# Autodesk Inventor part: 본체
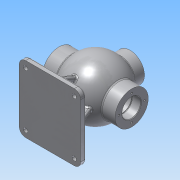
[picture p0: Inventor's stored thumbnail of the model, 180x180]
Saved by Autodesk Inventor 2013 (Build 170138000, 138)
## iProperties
Created: 2018-06
Part Number: 본체
Material: 알루미늄 6061
Document SubType Name: Modeling
Designer: Administrator
Density: 2.71 g/cm^3
Mass: 1509.58 g
Surface Area: 1153.7 cm^2
Volume: 557.041 cm^3
Author: Administrator
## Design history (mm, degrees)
sketch "스케치1"
  geometry: L1 (-68, 0)-(68, 0); L2 (-42.988, 31)-(-68, 31); L3 (-68, 31)-(-68, 17.5); L4 (-68, 17.5)-(-39.278, 17.5); L5 (42.988, 31)-(68, 31); L6 (68, 31)-(68, 17.5); L7 (50.25, 18.5)-(52, 18.5); L8 (52, 18.5)-(52, 17.5); L9 (50.25, 17.5)-(50.25, 18.5); L10 (68, 17.5)-(52, 17.5); L11 (50.25, 17.5)-(39.278, 17.5); A1 r 53 centre (0, 0) between (42.988, 31) and (-42.988, 31); A2 r 43 centre (0, 0) between (39.278, 17.5) and (-39.278, 17.5); 2 further points
  constraints: 22 end point, 6 parallel, 4 point on circle, 3 coincident, 3 perpendicular, 2 centre point, 2 horizontal, 2 point on line, 1 collinear, 1 midpoint
  dimensions: "d0" = 136 distance of L1.start L1.end; "d2" = 106 diameter of A1; "d3" = 86 diameter of A2; "d4" = 35 diameter of L4 L1; "d5" = 62 diameter of L2 L1; "d7" = 62 diameter of L5 L1; "d8" = 37 diameter of L7 L1; "d9" = 16 distance between parallel lines of L8 L6; "d10" = 1.75 distance of L7.start L7.end; "d11" = 35 diameter of L10 L1
revolve "회전1" sketch "스케치1" stored, may be unused: angle "d12" = 90 deg
sketch "스케치2"
  geometry: L1 (-57.5, -75)-(57.5, -75); L2 (57.5, -75)-(57.5, -85); L3 (57.5, -85)-(-57.5, -85); L4 (-57.5, -85)-(-57.5, -75); 2 further points
  constraints: 8 end point, 2 parallel, 1 horizontal, 1 midpoint, 1 perpendicular, 1 vertical alignment
  dimensions: "d13" = 115 distance of L2.end L3.end; "d15" = 85 distance from line of point (0, 0) L3; "d16" = 10 distance of L1.end L2.end
extrude "돌출1" join sketch "스케치2" stored distance "d17" = 125; taper "d18" = 0 deg
sketch "스케치3"
  geometry: L1 (0, 125)-(115, 125) reference; L2 (61.5, 10)-(53.5, 10); L3 (53.5, 10)-(53.5, 115); L4 (53.5, 115)-(61.5, 115); L5 (61.5, 115)-(61.5, 10); L6 (61.5, 10)-(53.5, 115); L7 (53.5, 10)-(61.5, 115); 1 further point
  constraints: 12 end point, 2 midpoint, 2 parallel, 1 horizontal, 1 perpendicular
  dimensions: "d19" = 8 distance of L3.end L4.end; "d20" = 10 distance between parallel lines of L1 L4
extrude "돌출2" join sketch "스케치3" stored distance "d21" = 125; taper "d22" = 0 deg
feature "면 기울기1" dims angle "d23" = 22 deg
sketch "스케치4"
  geometry: L1 (47.5, -75)-(40.471, -57.604); L2 (57.5, -75)-(57.5, -85) reference; L3 (-57.5, -75)-(57.5, -75) reference; 1 further point
  constraints: 2 end point, 1 point on line
  dimensions: "d24" = 22 deg angle of L1 L2; "d25" = 10 distance from line of L2 L1.start
feature "리브1" sketch "스케치4" dims "d26" = 1, "d27" = 8, "d28" = 0, "d29" = 0, "d30" = 1, "d31" = 1
node "작업 평면1"
sketch "스케치6"
  geometry: C1 r 27 at (-57.5, -62.5); 1 further point
  constraints: 1 centre point, 1 coincident
  dimensions: "d38" = 54 diameter of C1
extrude "돌출4" join sketch "스케치6" stored distance "d39" = 125; taper "d40" = 0 deg
sketch "스케치7"
  geometry: C1 r 27 at (0, 0) reference; C2 r 13 at (0, 0)
  constraints: 1 centre point, 1 coincident
  dimensions: "d41" = 26 diameter of C2
extrude "돌출5" cut sketch "스케치7" stored distance "d42" = 125; taper "d43" = 0 deg
node "작업 평면2"
sketch "스케치8" dims "d13" = 115, "d15" = 85, "d16" = 10
  geometry: L1 (-27, 0)-(27, 0) reference; 2 further points
  constraints: 1 other
  dimensions: "d44" = 10 distance from line of point (0, -10) L1; "d45" = 27 horizontal distance of L1.start point (0, -10)
feature "엠보싱1" sketch "스케치8" dims "d0" = 136, "d2" = 106, "d3" = 86, "d4" = 35, "d5" = 62, "d7" = 62, "d8" = 37, "d9" = 16, "d10" = 1.75, "d11" = 35, "d13" = 115, "d15" = 85, "d16" = 10, "d46" = 0.5, "d47" = 0
fillet "모깎기1" dims "d48" = 12
fillet "모깎기2" dims "d49" = 3
fillet "모깎기3" dims "d50" = 3
fillet "모깎기4" dims "d51" = 3
sketch "스케치9"
  geometry: C1 r 6 at (0, -9); C2 r 6 at (91, -9); 1 further point
  constraints: 2 centre point, 1 horizontal alignment
  dimensions: "d52" = 12 diameter of C1; "d53" = 12 diameter of C2; "d54" = 45.5 horizontal distance of point (45.5, -59.5) C1.centre; "d55" = 50.5 vertical distance of point (45.5, -59.5) C1.centre; "d56" = 45.5 horizontal distance of point (45.5, -59.5) C2.centre
extrude "돌출6" cut sketch "스케치9" distance "d57" = 3; taper "d58" = 0 deg
sketch "스케치10"
  geometry: C1 r 4 at (0, -9); C2 r 4 at (91, -9); A1 r 9 centre (91, -9) between (100, -9) and (91, 0) reference; A2 r 9 centre (0, -9) between (0, 0) and (-9, -9) reference; 1 further point
  constraints: 2 centre point, 2 coincident
  dimensions: "d59" = 8 diameter of C1; "d60" = 8 diameter of C2
extrude "돌출7" cut sketch "스케치10" stored distance "d61" = 3; taper "d62" = 0 deg
fillet "모깎기5" dims "d63" = 3
sketch "스케치11"
  geometry: C1 r 13 at (0, 0) reference; 1 further point
  constraints: 1 vertical alignment
  dimensions: "d68" = 20 distance of C1.centre point (0, 20)
hole "구멍1" sketch "스케치11" at (0, 20) diameter "d69" = 3.242; stored, may be unused: countersink angle "d73" = 90 deg, drill point angle "d75" = 118 deg; dims "d70" = 9, "d71" = 4, "d72" = 2, "d74" = 11
sketch "스케치12"
  geometry: C1 r 17.5 at (0, 0) reference; 1 further point
  constraints: 1 vertical alignment
  dimensions: "d79" = 22.5 distance of C1.centre point (0, 22.5)
sketch "스케치13"
  geometry: C1 r 17.5 at (0, 0) reference; 1 further point
  constraints: 1 vertical alignment
  dimensions: "d90" = 24 distance of C1.centre point (0, 24)
hole "구멍3" sketch "스케치13" at (0, 24) diameter "d91" = 3.242; stored, may be unused: countersink angle "d95" = 90 deg, drill point angle "d97" = 118 deg; dims "d92" = 16, "d93" = 4, "d94" = 2, "d96" = 19
hole "구멍4" sketch "스케치12" diameter "d98" = 3.242; stored, may be unused: countersink angle "d102" = 90 deg, drill point angle "d104" = 118 deg; dims "d99" = 12, "d100" = 4, "d101" = 2, "d103" = 15
chamfer "모따기2" distance "d111" = 1; stored, may be unused: second distance "d112" = 2, angle "d113" = 45 deg
node "솔리드1"
mirror "대칭1"
mirror "대칭2"
mirror "대칭3"
pattern_circular "원형 패턴1" dims angle "d77" = 360 deg
pattern_circular "원형 패턴3" dims angle "d106" = 360 deg
pattern_circular "원형 패턴4" dims angle "d109" = 360 deg
other parameters: "d6" = 35
